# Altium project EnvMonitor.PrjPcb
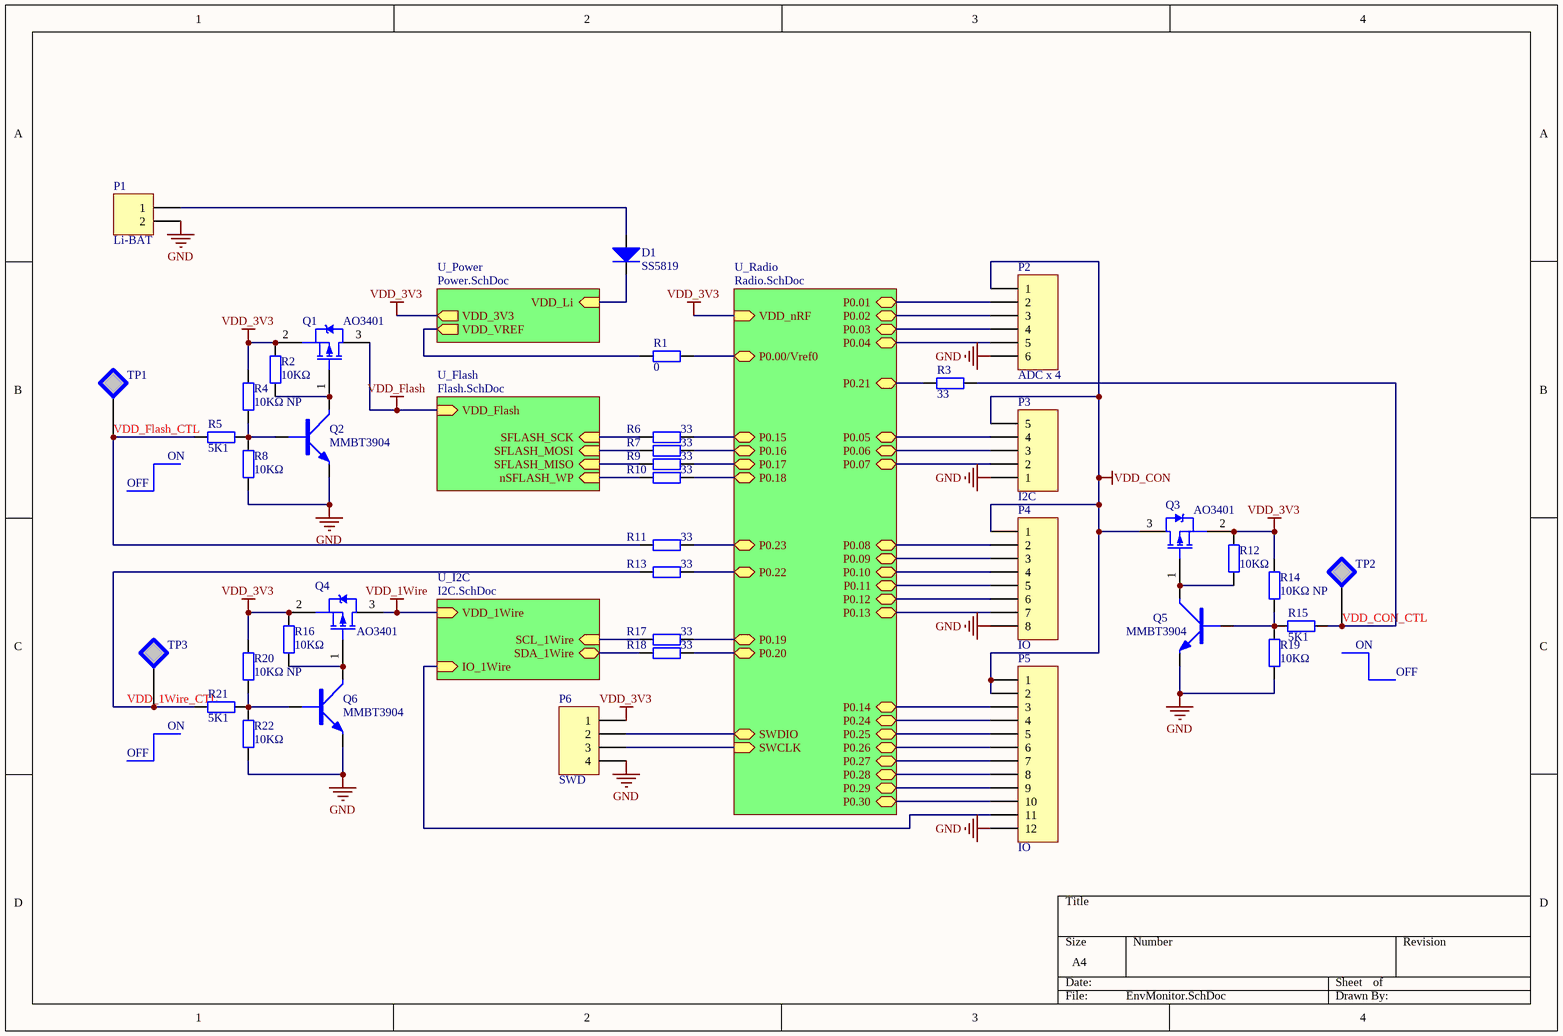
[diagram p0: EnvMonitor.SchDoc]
5 sheets, 102 parts. Net scope: hierarchical (ports join the sheet entries above them; power ports are global).
Sheets:
  EnvMonitor.SchDoc
    U_Radio = Radio.SchDoc
    U_Flash = Flash.SchDoc
    U_Power = Power.SchDoc
    U_I2C = I2C.SchDoc

## Sheet EnvMonitor.SchDoc
size A4

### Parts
D1  SS5819  [SMA]
P1  Li-BAT  [HDR1X2]
P2  ADC x 4  [HDR1X6]
P3  I2C  [HDR1X5]
P4  IO  [HDR1X8]
P5  IO  [HDR1X12]
P6  SWD  [HDR1X4]
Q1  AO3401  [SOT23]
Q2  MMBT3904  [SOT23]
Q3  AO3401  [SOT23]
Q4  AO3401  [SOT23]
Q5  MMBT3904  [SOT23]
Q6  MMBT3904  [SOT23]
R1  0  [0603]
R2  10KΩ  [0603]
R3  33  [0603]
R4  10KΩ NP  [0603]
R5  5K1  [0603]
R6  33  [0603]
R7  33  [0603]
R8  10KΩ  [0603]
R9  33  [0603]
R10  33  [0603]
R11  33  [0603]
R12  10KΩ  [0603]
R13  33  [0603]
R14  10KΩ NP  [0603]
R15  5K1  [0603]
R16  10KΩ  [0603]
R17  33  [0603]
R18  33  [0603]
R19  10KΩ  [0603]
R20  10KΩ NP  [0603]
R21  5K1  [0603]
R22  10KΩ  [0603]
TP1  (no value)  [TP-PAD1]  (no BOM)
TP2  (no value)  [TP-PAD1]  (no BOM)
TP3  (no value)  [TP-PAD1]  (no BOM)

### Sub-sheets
U_Flash = Flash.SchDoc: SFLASH_SCK (in), SFLASH_MOSI (in), SFLASH_MISO (in), nSFLASH_WP (in), VDD_Flash (in)
U_I2C = I2C.SchDoc: VDD_1Wire (in), IO_1Wire (in), SDA_1Wire (bidir), SCL_1Wire (in)
U_Power = Power.SchDoc: VDD_Li (in), VDD_3V3 (out), VDD_VREF (out)
U_Radio = Radio.SchDoc: SWDIO (bidir), SWCLK (in), P0.00/Vref0 (bidir), P0.01 (bidir), P0.02 (bidir), P0.03 (bidir), P0.04 (bidir), P0.05 (bidir), P0.06 (bidir), P0.07 (bidir), P0.08 (bidir), P0.09 (bidir), P0.10 (bidir), P0.11 (bidir), P0.12 (bidir), P0.13 (bidir), P0.14 (bidir), P0.15 (bidir), P0.16 (bidir), P0.17 (bidir), P0.18 (bidir), P0.19 (bidir), P0.20 (bidir), P0.21 (bidir), P0.22 (bidir), P0.23 (bidir), P0.24 (bidir), P0.25 (bidir), P0.26 (bidir), P0.27 (bidir), P0.28 (bidir), P0.29 (bidir), P0.30 (bidir), VDD_nRF (in)

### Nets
GND: P1.2 P2.6 P3.1 P4.8 P5.12 P6.4 Q2.2 Q5.2 Q6.2 R8.1 R19.1 R22.1
VDD_1Wire: Q4.3(D) ; sheet U_I2C/VDD_1Wire
VDD_3V3: P6.1 Q1.2(S) Q3.2(S) Q4.2(S) R2.2 R4.2 R12.2 R14.2 R16.2 R20.2 ; sheet U_Radio/VDD_nRF, sheet U_Power/VDD_3V3
VDD_CON: P2.1 P3.5 P4.1 P5.1 P5.2 Q3.3(D)
VDD_Flash: Q1.3(D) ; sheet U_Flash/VDD_Flash
nSFLASH_WP: R10.2 ; sheet U_Flash/nSFLASH_WP
P0.00/Vref0: R1.1 ; sheet U_Radio/P0.00/Vref0
P0.01: P2.2 ; sheet U_Radio/P0.01
P0.02: P2.3 ; sheet U_Radio/P0.02
P0.03: P2.4 ; sheet U_Radio/P0.03
P0.04: P2.5 ; sheet U_Radio/P0.04
P0.05: P3.4 ; sheet U_Radio/P0.05
P0.06: P3.3 ; sheet U_Radio/P0.06
P0.07: P3.2 ; sheet U_Radio/P0.07
P0.08: P4.2 ; sheet U_Radio/P0.08
P0.09: P4.3 ; sheet U_Radio/P0.09
P0.10: P4.4 ; sheet U_Radio/P0.10
P0.11: P4.5 ; sheet U_Radio/P0.11
P0.12: P4.6 ; sheet U_Radio/P0.12
P0.13: P4.7 ; sheet U_Radio/P0.13
P0.14: P5.3 ; sheet U_Radio/P0.14
P0.15: R6.1 ; sheet U_Radio/P0.15
P0.16: R7.1 ; sheet U_Radio/P0.16
P0.17: R9.1 ; sheet U_Radio/P0.17
P0.18: R10.1 ; sheet U_Radio/P0.18
P0.19: R17.1 ; sheet U_Radio/P0.19
P0.20: R18.1 ; sheet U_Radio/P0.20
P0.21: R3.1 ; sheet U_Radio/P0.21
P0.22: R13.1 ; sheet U_Radio/P0.22
P0.23: R11.1 ; sheet U_Radio/P0.23
P0.24: P5.4 ; sheet U_Radio/P0.24
P0.25: P5.5 ; sheet U_Radio/P0.25
P0.26: P5.6 ; sheet U_Radio/P0.26
P0.27: P5.7 ; sheet U_Radio/P0.27
P0.28: P5.8 ; sheet U_Radio/P0.28
P0.29: P5.9 ; sheet U_Radio/P0.29
P0.30: P5.10 ; sheet U_Radio/P0.30
SFLASH_MISO: R9.2 ; sheet U_Flash/SFLASH_MISO
SFLASH_MOSI: R7.2 ; sheet U_Flash/SFLASH_MOSI
SFLASH_SCK: R6.2 ; sheet U_Flash/SFLASH_SCK
SWCLK: P6.3 ; sheet U_Radio/SWCLK
SWDIO: P6.2 ; sheet U_Radio/SWDIO
VDD_1Wire_CTL: R13.2 R21.2 TP3.1
VDD_CON_CTL: R3.2 R15.2 TP2.1
VDD_Flash_CTL: R5.2 R11.2 TP1.1
VDD_Li: D1.2(K) ; sheet U_Power/VDD_Li
VDD_VREF: R1.2 ; sheet U_Power/VDD_VREF
NetD1_1: D1.1(A) P1.1
NetP5_11: P5.11 ; sheet U_I2C/IO_1Wire
NetQ1_1: Q1.1(G) Q2.3 R2.1
NetQ2_1: Q2.1 R4.1 R5.1 R8.2
NetQ3_1: Q3.1(G) Q5.3 R12.1
NetQ4_1: Q4.1(G) Q6.3 R16.1
NetQ5_1: Q5.1 R14.1 R15.1 R19.2
NetQ6_1: Q6.1 R20.1 R21.1 R22.2
NetR17_2: R17.2 ; sheet U_I2C/SCL_1Wire
NetR18_2: R18.2 ; sheet U_I2C/SDA_1Wire

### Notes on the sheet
- OFF
- (near R5) ON
- (near R15) ON
- (near R21) ON

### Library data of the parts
D1 = Diode 1N4001
P1 = Header 2: Header, 2-Pin
P2 = Header 6: Header, 6-Pin
P3 = Header 5: Header, 5-Pin
P4 = Header 8: Header, 8-Pin
P5 = Header 12: Header, 12-Pin
P6 = Header 4: Header, 4-Pin
Q1 Q3 Q4 = DMP3098L: -30V,-3.8A   PMOS  70-120mΩ; Manufacturer: DIODES; Kind: 贴片MOS管; Remark: 关键元器件
Q2 Q5 Q6 = 9013: NPN三极管; Kind: 贴片三极管
R1-R22 = RES_0603
TP1-TP3 = TESTPOINT: Test Point

## Sheet Radio.SchDoc: PCA100024 - Radio
size A4; Revision: 1.0.0; SheetNumber: 1; SheetTotal: 3; DrawnBy: RUBR; ProjectNumber: 4400; PCBRevision: 0141RUBR; DocumentSize: A4; PCAName: PCA10024; PCBNumber: 400081
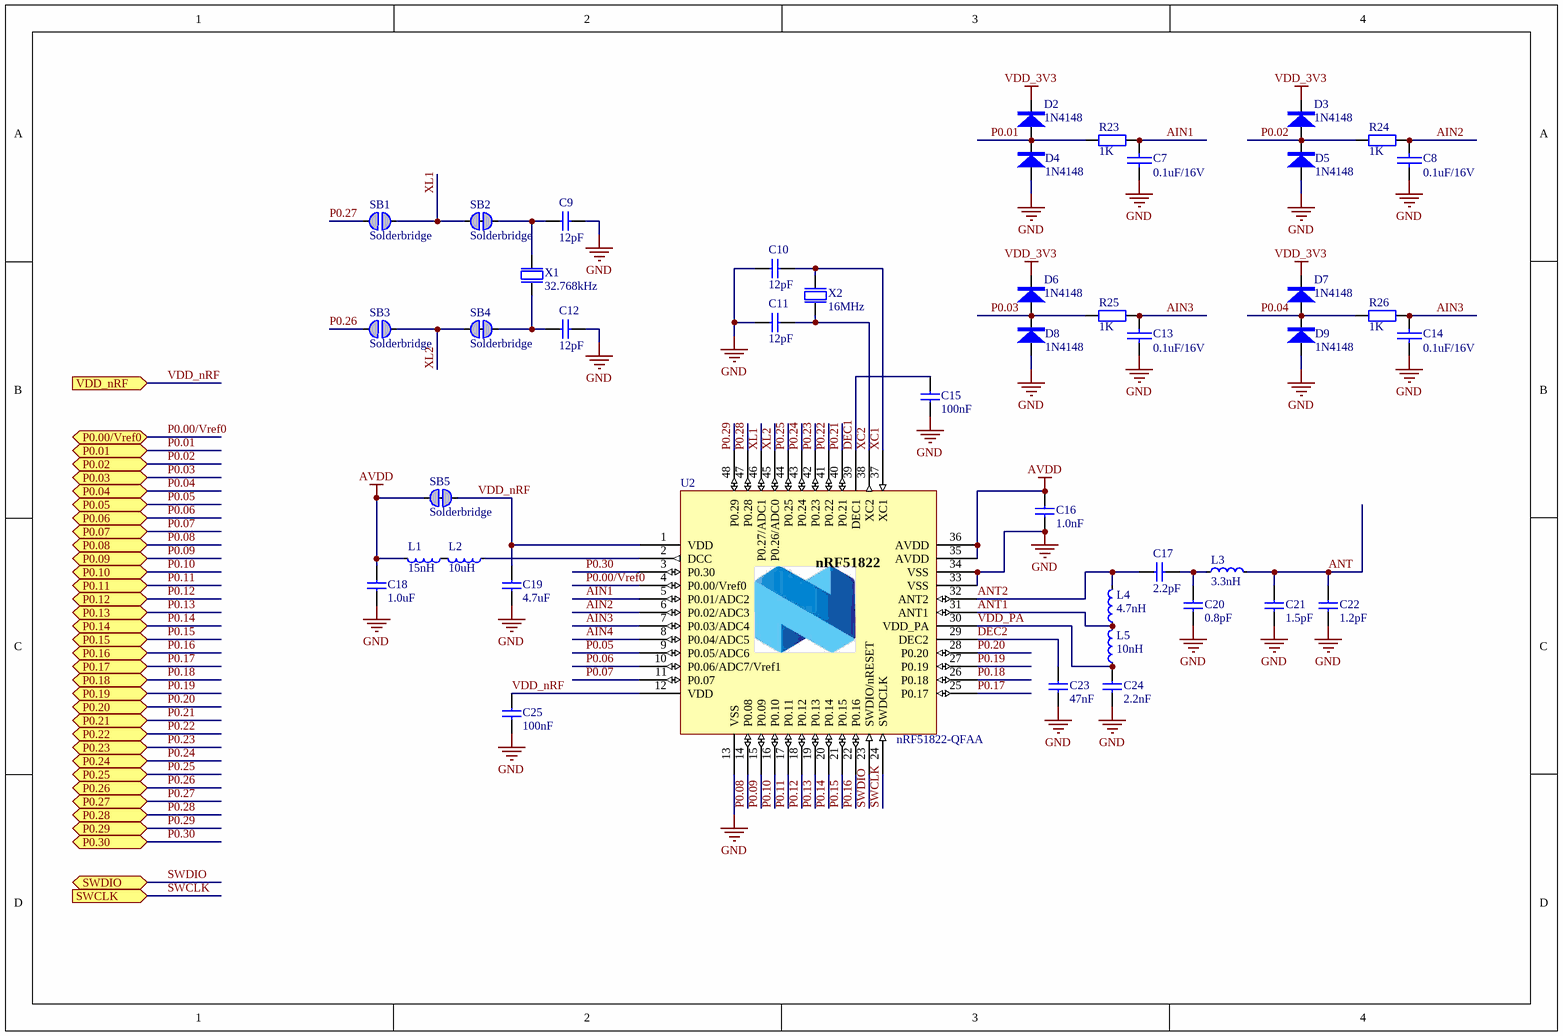
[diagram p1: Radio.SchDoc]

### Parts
C7  0.1uF/16V  [0603]
C8  0.1uF/16V  [0603]
C9  12pF  [0603]
C10  12pF  [0603]
C11  12pF  [0603]
C12  12pF  [0603]
C13  0.1uF/16V  [0603]
C14  0.1uF/16V  [0603]
C15  100nF  [0603]
C16  1.0nF  [0603]
C17  2.2pF  [0603]
C18  1.0uF  [0603]
C19  4.7uF  [0603]
C20  0.8pF  [0603]
C21  1.5pF  [0603]
C22  1.2pF  [0603]
C23  47nF  [0603]
C24  2.2nF  [0603]
C25  100nF  [0603]
D2  1N4148  [SMA]
D3  1N4148  [SMA]
D4  1N4148  [SMA]
D5  1N4148  [SMA]
D6  1N4148  [SMA]
D7  1N4148  [SMA]
D8  1N4148  [SMA]
D9  1N4148  [SMA]
L1  15nH  [0603]
L2  10uH  [0603]
L3  3.3nH  [0603]
L4  4.7nH  [0603]
L5  10nH  [0603]
R23  1K  [0603]
R24  1K  [0603]
R25  1K  [0603]
R26  1K  [0603]
SB1  Solderbridge  [Solderbridge]  (no BOM)
SB2  Solderbridge  [Solderbridge_Shorted]  (net tie, no BOM)
SB3  Solderbridge  [Solderbridge]  (no BOM)
SB4  Solderbridge  [Solderbridge_Shorted]  (net tie, no BOM)
SB5  Solderbridge  [Solderbridge_Shorted]  (net tie, no BOM)
U2  nRF51822-QFAA  [QFN40P600X600X90-48N]
X1  32.768kHz  [FC-135]
X2  16MHz  [BT-XTAL_2520]

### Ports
P0.00/Vref0 (bidir), P0.01 (bidir), P0.02 (bidir), P0.03 (bidir), P0.04 (bidir), P0.05 (bidir), P0.06 (bidir), P0.07 (bidir), P0.08 (bidir), P0.09 (bidir), P0.10 (bidir), P0.11 (bidir), P0.12 (bidir), P0.13 (bidir), P0.14 (bidir), P0.15 (bidir), P0.16 (bidir), P0.17 (bidir), P0.18 (bidir), P0.19 (bidir), P0.20 (bidir), P0.21 (bidir), P0.22 (bidir), P0.23 (bidir), P0.24 (bidir), P0.25 (bidir), P0.26 (bidir), P0.27 (bidir), P0.28 (bidir), P0.29 (bidir), P0.30 (bidir), SWCLK (in), SWDIO (bidir), VDD_nRF (in)

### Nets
AVDD: C16.1 C18.2 L1.2 SB5.2 U2.35(AVDD) U2.36(AVDD)
GND: C7.2(P2) C8.2(P2) C9.2 C10.2 C11.2 C12.2 C13.2(P2) C14.2(P2) C15.2 C16.2 C18.1 C19.2 C20.2 C21.2 C22.2 C23.2 C24.2 C25.2 D4.1 D5.1 D8.1 D9.1 U2.13(VSS) U2.33(VSS) U2.34(VSS) U2.49 X2.2(GND) X2.4(GND)
VDD_3V3: C19.1 C25.1 D2.2 D3.2 D6.2 D7.2 SB5.1 U2.1(VDD) U2.12(VDD) ; port VDD_nRF  [also labelled VDD_nRF]
AIN1: C7.1(P1) R23.2 U2.5(P0.01/ADC2)
AIN2: C8.1(P1) R24.2 U2.6(P0.02/ADC3)
AIN3: C13.1(P1) C14.1(P1) R25.2 R26.2 U2.7(P0.03/ADC4)
AIN4: U2.8(P0.04/ADC5)
ANT: C21.1 C22.1 L3.2
ANT1: L4.1 L5.2 U2.31(ANT1)
ANT2: C17.1 L4.2 U2.32(ANT2)
DEC1: C15.1 U2.39(DEC1)
DEC2: C23.1 U2.29(DEC2)
P0.00/Vref0: U2.4(P0.00/Vref0) ; port P0.00/Vref0
P0.01: D2.1 D4.2 R23.1 ; port P0.01
P0.02: D3.1 D5.2 R24.1 ; port P0.02
P0.03: D6.1 D8.2 R25.1 ; port P0.03
P0.04: D7.1 D9.2 R26.1 ; port P0.04
P0.05: U2.9(P0.05/ADC6) ; port P0.05
P0.06: U2.10(P0.06/ADC7/Vref1) ; port P0.06
P0.07: U2.11(P0.07) ; port P0.07
P0.08: U2.14(P0.08) ; port P0.08
P0.09: U2.15(P0.09) ; port P0.09
P0.10: U2.16(P0.10) ; port P0.10
P0.11: U2.17(P0.11) ; port P0.11
P0.12: U2.18(P0.12) ; port P0.12
P0.13: U2.19(P0.13) ; port P0.13
P0.14: U2.20(P0.14) ; port P0.14
P0.15: U2.21(P0.15) ; port P0.15
P0.16: U2.22(P0.16) ; port P0.16
P0.17: U2.25(P0.17) ; port P0.17
P0.18: U2.26(P0.18) ; port P0.18
P0.19: U2.27(P0.19) ; port P0.19
P0.20: U2.28(P0.20) ; port P0.20
P0.21: U2.40(P0.21) ; port P0.21
P0.22: U2.41(P0.22) ; port P0.22
P0.23: U2.42(P0.23) ; port P0.23
P0.24: U2.43(P0.24) ; port P0.24
P0.25: U2.44(P0.25) ; port P0.25
P0.26: SB3.2 ; port P0.26
P0.27: SB1.2 ; port P0.27
P0.28: U2.47(P0.28) ; port P0.28
P0.29: U2.48(P0.29) ; port P0.29
P0.30: U2.3(P0.30) ; port P0.30
SWCLK: U2.24(SWDCLK) ; port SWCLK
SWDIO: U2.23(SWDIO/nRESET) ; port SWDIO
VDD_PA: C24.1 L5.1 U2.30(VDD_PA)
XC1: C10.1 U2.37(XC1) X2.1(inp)
XC2: C11.1 U2.38(XC2) X2.3(out)
XL1: SB1.1 SB2.2 U2.46(P0.27/ADC1)
XL2: SB3.1 SB4.2 U2.45(P0.26/ADC0)
NetC9_1: C9.1 SB2.1 X1.2(out)
NetC12_1: C12.1 SB4.1 X1.1(inp)
NetC17_2: C17.2 C20.1 L3.1
NetL1_1: L1.1 L2.2
NetL2_1: L2.1 U2.2(DCC)

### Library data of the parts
C7 C8 C13 C14 = CAP: 贴片陶瓷电容
C9-C12 = C0402-12p: Capacitor, NP0, ?%; Note: 50V; Artikkelnr Noca: 20029159
C15 C25 = C0402-100n: Capacitor, X7R, ?0%; Note: 16V; Artikkelnr Noca: 20039200
C16 = C0402-1n0: Capacitor, X7R, ?0%; Note: 50V; Artikkelnr Noca: 20039223
C17 = C0402-2.2p: Capacitor, NP0, ?.1pF; Note: 50V; Artikkelnr Noca: 20029145
C18 = C0603-1?: Capacitor, X7R, ?0%; Value: 1.0µF; Note: 16V; Artikkelnr Noca: 20039335
C19 = C0603-4?: Capacitor, X5R, ?0%; Value: 4.7µF; Note: 6.3V; Artikkelnr Noca: 20069060
C20 = C0402-0.8p: Capacitor, NP0, ?%; Note: 50V; Artikkelnr Noca: 20029147
C21 = C0402-1.5p: Capacitor, NP0, ?.1pF; Note: 50V; Artikkelnr Noca: 20029139
C22 = C0402-1.2p: Capacitor, NP0, ?.1pF; Note: 50V; Artikkelnr Noca: 20029157
C23 = C0402-47n: Capacitor, X7R, ?0%; Note: Chip Cap 10%; Artikkelnr Noca: 20039389
C24 = C0402-2n2: Capacitor, X7R, ?0%; Note: 50V; Artikkelnr Noca: 20039221
D2-D9 = DIODE: 贴片二极管; Remark: 可用1N5819替代
L1 = L0402-15n: Inductor, 320mA, ?%; Manufacturer: Taiyo Yuden; Manufacturer Part Number: HK100515NJ-T; 2nd source part number: 658-1328; Note: High frequency chip inductor ?0%; Artikkelnr Noca: 33029323
L2 = L0603-10?: Inductor, 80mA, ?0%; Part Number: L0603-10祹ISHIDDEN=T; Manufacturer: Taiyo Yuden; Manufacturer Part Number: LBMF1608T100K; 2nd source part number: 178-6105; Value: 10µH; Note: LBMF1608T100K 10µH 80mA 0603; Artikkelnr Noca: 33029314
L3 = L0402-3n3: Inductor, 190mA, ?.1nH; Manufacturer: Murata; Manufacturer Part Number: LQP15MN3N3B02D; Note: High frequency chip inductor ?%; Artikkelnr Noca: 33029369
L4 = L0402-4n7: Inductor, 160mA, ?.1nH; Manufacturer: Murata; Manufacturer Part Number: LQP15MN4N7B02D; Note: High frequency chip inductor ?%; Artikkelnr Noca: 33029164
L5 = L0402-10n: Inductor, 100mA, ?%; Manufacturer: Murata; Manufacturer Part Number: LQP15MN10NG02D; Note: High frequency chip inductor ?%; Artikkelnr Noca: 33029425
R23-R26 = RES_0603
SB1 SB3 = Solderbridge: Artikkelnr Noca: N.A.
SB2 SB4 SB5 = Solderbridge Shorted: Shorted Solderbridge; Artikkelnr Noca: N.A.
U2 = nRF51822_QFAA: Multi-protocol Bluetooth Low Energy and 2.4GHz proprietary system-on-chip; Part Number: nRF51822-QFAA-XLR2.4; Manufacturer: Nordic Semiconductor; Manufacturer Part Number: nRF51822-QFAAGx; Note: nRF51822 - QFN48 6x6 0.4mm pitch; Artikkelnr Noca: 15079242
X1 = XTAL_FC-135 32.768k: EPSON TOYOCOM - FC-135 32.768KHZ ?0PPM,9.0PF - CRYSTAL, SM, WATCH; 2nd source part number: 127-8037; Note: XTAL SMD 32.768kHz, 3215; Artikkelnr Noca: 22019091
X2 = NX2520SA-16MHZ-STD-CSW-5: XTAL SMD 2520, 16MHz, 8pF, ?5ppm; Manufacturer: NDK; Note: XTAL SMD 16.000MHz; Artikkelnr Noca: 22019192

## Sheet Flash.SchDoc
size A4
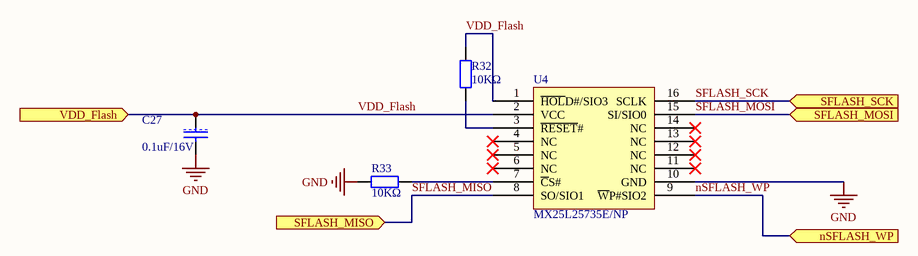
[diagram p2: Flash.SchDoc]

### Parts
C27  0.1uF/16V  [0603]  (no BOM)
R32  10KΩ  [0603]
R33  10KΩ  [0603]
U4  MX25L25735E/NP  [SOIC16W]  (no BOM)

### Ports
nSFLASH_WP (in), SFLASH_MISO (in), SFLASH_MOSI (in), SFLASH_SCK (in), VDD_Flash (in)

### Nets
GND: C27.2 R33.2 U4.10(GND)
VDD_Flash: C27.1 R32.2 U4.1(~{HOL}D#/SIO3) U4.2(VCC) ; port VDD_Flash
nSFLASH_WP: U4.9(~{W}P#SIO2) ; port nSFLASH_WP
SFLASH_MISO: U4.8(SO/SIO1) ; port SFLASH_MISO
SFLASH_MOSI: U4.15(SI/SIO0) ; port SFLASH_MOSI
SFLASH_SCK: U4.16(SCLK) ; port SFLASH_SCK
NetR32_1: R32.1 U4.3(~{RESET}#)
NetR33_1: R33.1 U4.7(~{C}S#)

Not connected (* = marked no-connect by the designer): U4 4(NC)* 5(NC)* 6(NC)* 11(NC)* 12(NC)* 13(NC)* 14(NC)*

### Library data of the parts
C27 = CAP: 贴片陶瓷电容
R32 R33 = RES_0603
U4 = MX25L25735E: SPI_flash; Manufacturer: MXIC; Kind: 集成电路; Remark: 关键元器件; 规格: 16-PIN SOP(300mil)

## Sheet Power.SchDoc
size A4
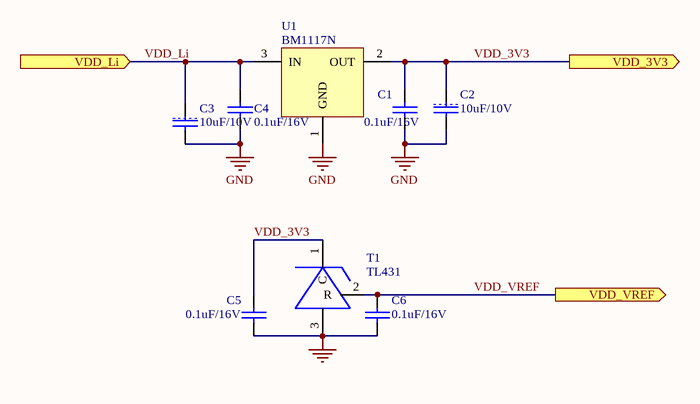
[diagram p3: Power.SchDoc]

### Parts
C1  0.1uF/16V  [0603]
C2  10uF/10V  [0805]
C3  10uF/10V  [0805]
C4  0.1uF/16V  [0603]
C5  0.1uF/16V  [0603]
C6  0.1uF/16V  [0603]
T1  TL431  [so-8]
U1  BM1117N  [TO-252]

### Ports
VDD_3V3 (out), VDD_Li (in), VDD_VREF (out)

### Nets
GND: C1.2 C2.2 C3.2 C4.2 C5.2 C6.2 T1.3 U1.1(GND)
VDD_3V3: C1.1 C2.1 C5.1 T1.1(C) U1.2(OUT) ; port VDD_3V3
VDD_Li: C3.1 C4.1 U1.3(IN) ; port VDD_Li
VDD_VREF: C6.1 T1.2(R) ; port VDD_VREF

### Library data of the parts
C1-C6 = CAP: 贴片陶瓷电容
U1 = AZ1084

## Sheet I2C.SchDoc
size A4
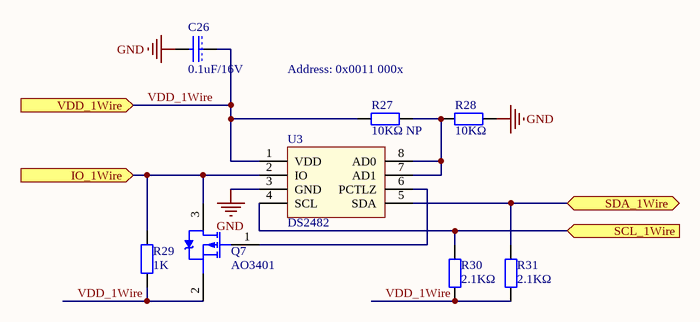
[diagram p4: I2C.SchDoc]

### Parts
C26  0.1uF/16V  [0603]  (no BOM)
Q7  AO3401  [SOT23]
R27  10KΩ NP  [0603]
R28  10KΩ  [0603]
R29  1K  [0603]
R30  2.1KΩ  [0603]
R31  2.1KΩ  [0603]
U3  DS2482

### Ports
IO_1Wire (in), SCL_1Wire (in), SDA_1Wire (bidir), VDD_1Wire (in)

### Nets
GND: C26.2 R28.1 U3.3(GND)
VDD_1Wire: C26.1 Q7.2(S) R27.2 R29.1 R30.2 R31.2 U3.1(VDD) ; port VDD_1Wire
NetP5_11: Q7.3(D) R29.2 U3.2(IO) ; port IO_1Wire
NetQ7_1: Q7.1(G) U3.6(PCTLZ)
NetR17_2: R30.1 U3.4(SCL) ; port SCL_1Wire
NetR18_2: R31.1 U3.5(SDA) ; port SDA_1Wire
NetR27_1: R27.1 R28.2 U3.7(AD1) U3.8(AD0)

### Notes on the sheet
- Address: 0x0011 000x

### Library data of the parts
C26 = CAP: 贴片陶瓷电容
Q7 = DMP3098L: as Q1 on sheet EnvMonitor
R27-R31 = RES_0603

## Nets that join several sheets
GND: EnvMonitor (12 pins), Radio (28 pins), Flash (C27.2 R33.2 U4.10), Power (8 pins), I2C (C26.2 R28.1 U3.3)
VDD_1Wire: EnvMonitor (Q4.3), I2C (7 pins)
VDD_3V3: EnvMonitor (10 pins), Radio (9 pins), Power (5 pins)
VDD_Flash: EnvMonitor (Q1.3), Flash (C27.1 R32.2 U4.1 U4.2)
NetP5_11: EnvMonitor (P5.11), I2C (Q7.3 R29.2 U3.2)
NetR17_2: EnvMonitor (R17.2), I2C (R30.1 U3.4)
NetR18_2: EnvMonitor (R18.2), I2C (R31.1 U3.5)
nSFLASH_WP: EnvMonitor (R10.2), Flash (U4.9)
P0.00/Vref0: EnvMonitor (R1.1), Radio (U2.4)
P0.01: EnvMonitor (P2.2), Radio (D2.1 D4.2 R23.1)
P0.02: EnvMonitor (P2.3), Radio (D3.1 D5.2 R24.1)
P0.03: EnvMonitor (P2.4), Radio (D6.1 D8.2 R25.1)
P0.04: EnvMonitor (P2.5), Radio (D7.1 D9.2 R26.1)
P0.05: EnvMonitor (P3.4), Radio (U2.9)
P0.06: EnvMonitor (P3.3), Radio (U2.10)
P0.07: EnvMonitor (P3.2), Radio (U2.11)
P0.08: EnvMonitor (P4.2), Radio (U2.14)
P0.09: EnvMonitor (P4.3), Radio (U2.15)
P0.10: EnvMonitor (P4.4), Radio (U2.16)
P0.11: EnvMonitor (P4.5), Radio (U2.17)
P0.12: EnvMonitor (P4.6), Radio (U2.18)
P0.13: EnvMonitor (P4.7), Radio (U2.19)
P0.14: EnvMonitor (P5.3), Radio (U2.20)
P0.15: EnvMonitor (R6.1), Radio (U2.21)
P0.16: EnvMonitor (R7.1), Radio (U2.22)
P0.17: EnvMonitor (R9.1), Radio (U2.25)
P0.18: EnvMonitor (R10.1), Radio (U2.26)
P0.19: EnvMonitor (R17.1), Radio (U2.27)
P0.20: EnvMonitor (R18.1), Radio (U2.28)
P0.21: EnvMonitor (R3.1), Radio (U2.40)
P0.22: EnvMonitor (R13.1), Radio (U2.41)
P0.23: EnvMonitor (R11.1), Radio (U2.42)
P0.24: EnvMonitor (P5.4), Radio (U2.43)
P0.25: EnvMonitor (P5.5), Radio (U2.44)
P0.26: EnvMonitor (P5.6), Radio (SB3.2)
P0.27: EnvMonitor (P5.7), Radio (SB1.2)
P0.28: EnvMonitor (P5.8), Radio (U2.47)
P0.29: EnvMonitor (P5.9), Radio (U2.48)
P0.30: EnvMonitor (P5.10), Radio (U2.3)
SFLASH_MISO: EnvMonitor (R9.2), Flash (U4.8)
SFLASH_MOSI: EnvMonitor (R7.2), Flash (U4.15)
SFLASH_SCK: EnvMonitor (R6.2), Flash (U4.16)
SWCLK: EnvMonitor (P6.3), Radio (U2.24)
SWDIO: EnvMonitor (P6.2), Radio (U2.23)
VDD_Li: EnvMonitor (D1.2), Power (C3.1 C4.1 U1.3)
VDD_VREF: EnvMonitor (R1.2), Power (C6.1 T1.2)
